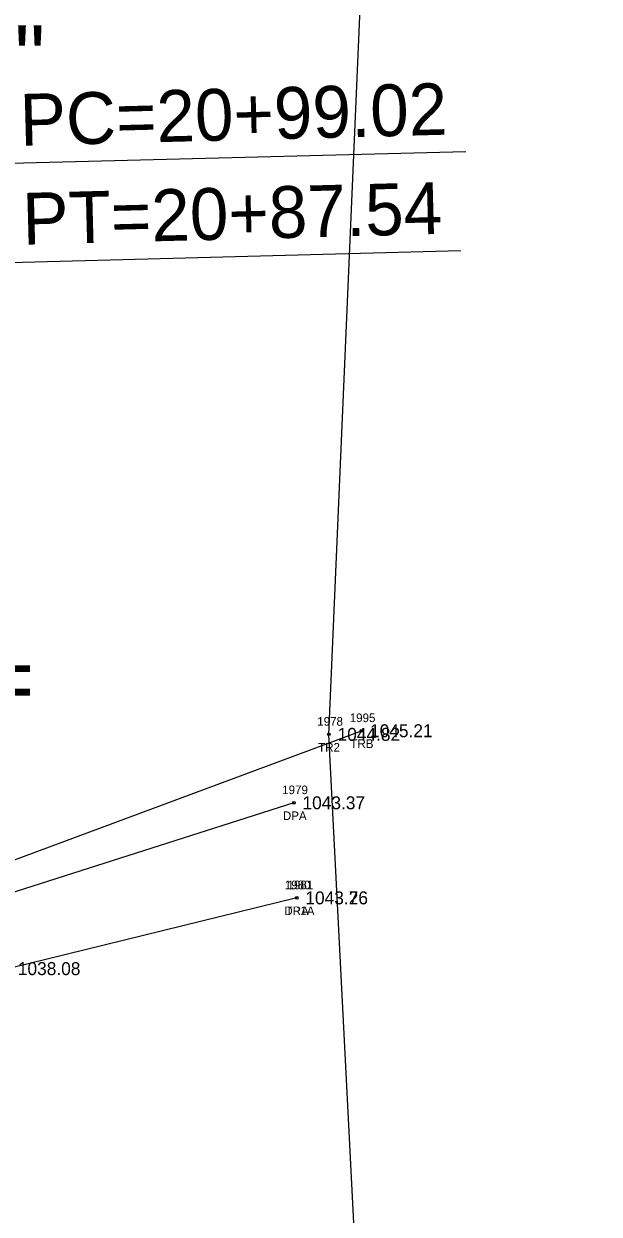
# Model space of a CAD drawing. Extents: x 1578957 to 1581675, y 1115963 to 1120391.
# Drawn here: x 1580116.1 to 1580182.8, y 1117317.7 to 1117455.7 of the extents above; entities that cross this region are included whole.
import ezdxf

# ---------------------------------------------------------------- set-up
doc = ezdxf.new("R2010")
doc.units = 0
for name, color, linetype in [('RD_EX_Driveway', 7, 'Continuous'), ('RD_EX_Driveway_txCode', 7, 'Continuous'), ('RD_EX_TX_Driveway_ELEV', 7, 'Continuous'), ('RD_EX_TX_VEG_ELEV', 7, 'Continuous'), ('RD_EX_VEG', 7, 'Continuous'), ('RD_EX_VEG_txCode', 7, 'Continuous'), ('RD_HC_Data', 7, 'Continuous'), ('RD_SMD_Locator', 7, 'Continuous')]:
    doc.layers.add(name, color=color, linetype=linetype)

msp = doc.modelspace()

# ---------------------------------------------------------------- linework, layer by layer
at = {"layer": 'RD_EX_Driveway'}
for points in [[(1580147.42, 1117365.4), (1580095.15, 1117348.71), (1580078.2, 1117343.39), (1580073.91, 1117343.49)], [(1580147.75, 1117354.38), (1580114.45, 1117346.18), (1580096.71, 1117337.8), (1580086.52, 1117329.67), (1580077.73, 1117318.61), (1580073.91, 1117343.49)]]:
    msp.add_lwpolyline(points, dxfattribs=at)
at = {"layer": 'RD_EX_VEG'}
msp.add_line((1580073.91, 1117343.49), (1580155.24, 1117373.75), dxfattribs=at)
for points in [[(1580197.82, 1117040.79), (1580158.29, 1117196.48), (1580160.39, 1117232.83), (1580157.11, 1117263.14), (1580151.48, 1117373.33), (1580156, 1117478.09)], [(1580147.75, 1117354.38), (1580114.45, 1117346.18), (1580077.73, 1117318.61)]]:
    msp.add_lwpolyline(points, dxfattribs=at)
at = {"layer": 'RD_HC_Data'}
for p, q in [((1580050.82, 1117437.85), (1580167.35, 1117440.89)), ((1580051.12, 1117426.37), (1580166.75, 1117429.39))]:
    msp.add_line(p, q, dxfattribs=at)
at = {"layer": 'RD_SMD_Locator'}
for centre in [(1580151.48, 1117373.33), (1580155.24, 1117373.75), (1580147.42, 1117365.4), (1580147.75, 1117354.38), (1580147.75, 1117354.38)]:
    msp.add_circle(centre, 0.15, dxfattribs=at)

# ---------------------------------------------------------------- texts
at = {"layer": 'RD_EX_Driveway_txCode'}
for s, p in [('1979', (1580146.07, 1117366.4)), ('DPA', (1580146.15, 1117363.4)), ('1980', (1580146.37, 1117355.38)), ('DP1A', (1580146.32, 1117352.38))]:
    msp.add_text(s, height=1, dxfattribs=at).set_placement(p)
at = {"layer": 'RD_EX_TX_Driveway_ELEV'}
for s, p in [('1043.37', (1580148.42, 1117364.65)), ('1043.26', (1580148.75, 1117353.63)), ('1038.08', (1580115.45, 1117345.43))]:
    msp.add_text(s, height=1.5, dxfattribs=at).set_placement(p)
at = {"layer": 'RD_EX_TX_VEG_ELEV'}
for s, p in [('1045.21', (1580156.24, 1117373)), ('1044.82', (1580152.48, 1117372.58)), ('1043.76', (1580148.75, 1117353.63)), ('1038.08', (1580115.45, 1117345.43))]:
    msp.add_text(s, height=1.5, dxfattribs=at).set_placement(p)
at = {"layer": 'RD_EX_VEG_txCode'}
for s, p in [('1995', (1580153.89, 1117374.75)), ('1978', (1580150.13, 1117374.33)), ('TR2', (1580150.23, 1117371.33)), ('TRB', (1580153.97, 1117371.75)), ('1981', (1580146.69, 1117355.38)), ('TRA', (1580146.47, 1117352.38))]:
    msp.add_text(s, height=1, dxfattribs=at).set_placement(p)
at = {"layer": 'RD_HC_Data'}
for s, p in [('D = 8%%d 44\' 38"', (1580057, 1117448)), ('P.C. - LG% = ', (1580058, 1117376))]:
    msp.add_text(s, height=7.5, dxfattribs=at).set_placement(p)
for s, p in [('PC=20+99.02', (1580115.75, 1117441.54)), ('PT=20+87.54', (1580116.05, 1117430.07))]:
    msp.add_text(s, height=6, rotation=1.4941, dxfattribs=at).set_placement(p)

doc.saveas('drawing.dxf')
